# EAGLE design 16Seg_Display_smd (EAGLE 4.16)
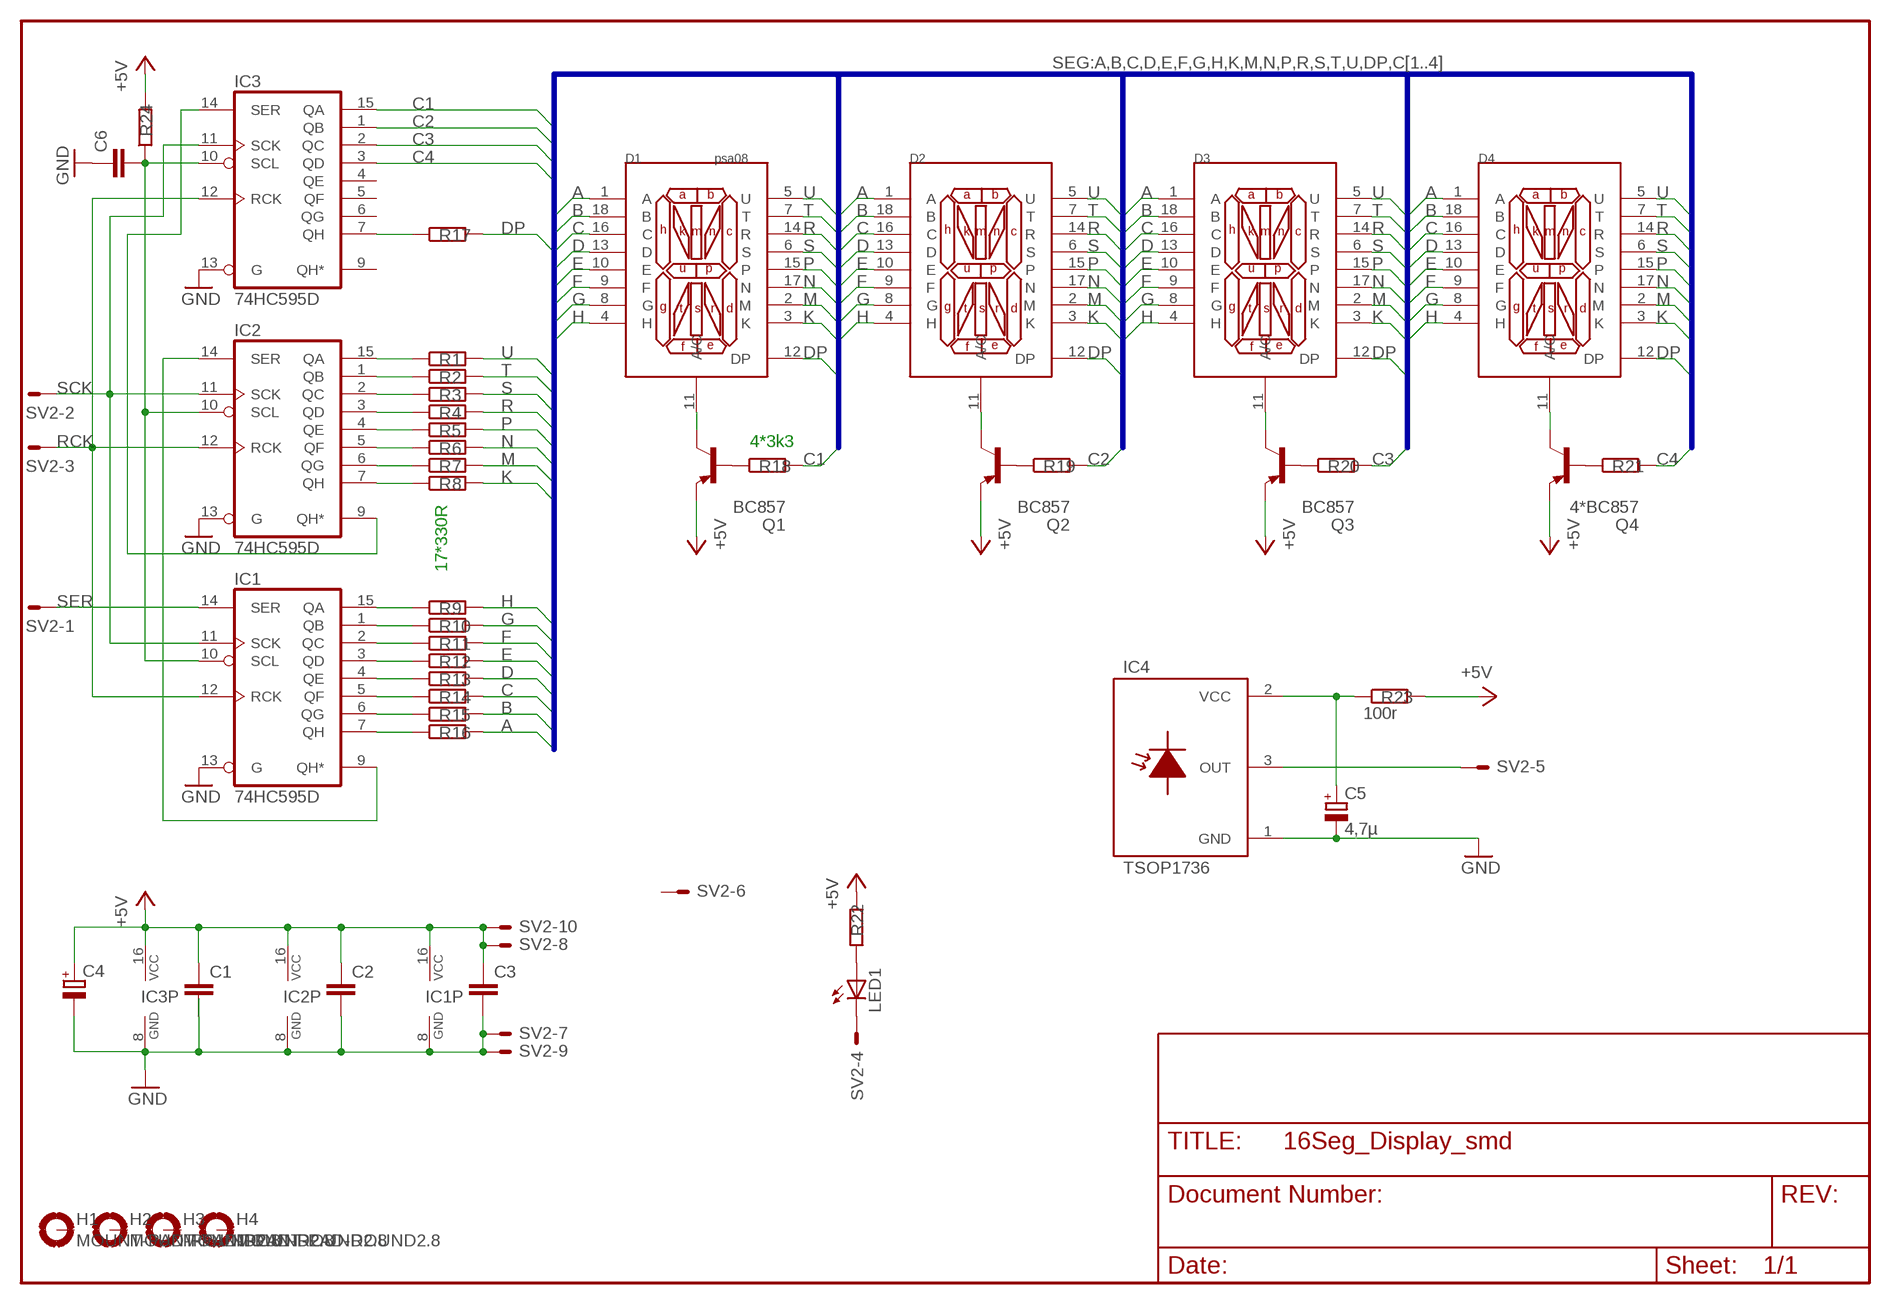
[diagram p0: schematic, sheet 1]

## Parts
C1  C-EUC0805K  [C0805K]
C2  C-EUC0805K  [C0805K]
C3  C-EUC0805K  [C0805K]
C4  CPOL-EUE2-5  [E2-5]
C5  4,7µ  CPOL-EUE2-5  [E2-5]
C6  C-EUC0805K  [C0805K]
D1  psa08  PSA08-11  [MSA08-11]
D2  PSA08-11  [MSA08-11]
D3  PSA08-11  [MSA08-11]
D4  PSA08-11  [MSA08-11]
H1  MOUNT-PAD-ROUND2.8  [2,8-PAD]
H2  MOUNT-PAD-ROUND2.8  [2,8-PAD]
H3  MOUNT-PAD-ROUND2.8  [2,8-PAD]
H4  MOUNT-PAD-ROUND2.8  [2,8-PAD]
IC1  74HC595D  [SO16]
IC2  74HC595D  [SO16]
IC3  74HC595D  [SO16]
IC4  TSOP1736  [TSOP]
LED1  LED3MM  [LED3MM]
Q1  BC857  BC857BSMD  [SOT23-BEC]
Q2  BC857  BC857BSMD  [SOT23-BEC]
Q3  BC857  BC857BSMD  [SOT23-BEC]
Q4  4*BC857  BC857BSMD  [SOT23-BEC]
R1  R-EU_M0805  [M0805]
R2  R-EU_M0805  [M0805]
R3  R-EU_M0805  [M0805]
R4  R-EU_M0805  [M0805]
R5  R-EU_M0805  [M0805]
R6  R-EU_M0805  [M0805]
R7  R-EU_M0805  [M0805]
R8  R-EU_M0805  [M0805]
R9  R-EU_M0805  [M0805]
R10  R-EU_M0805  [M0805]
R11  R-EU_M0805  [M0805]
R12  R-EU_M0805  [M0805]
R13  R-EU_M0805  [M0805]
R14  R-EU_M0805  [M0805]
R15  R-EU_M0805  [M0805]
R16  R-EU_M0805  [M0805]
R17  R-EU_M0805  [M0805]
R18  R-EU_M0805  [M0805]
R19  R-EU_M0805  [M0805]
R20  R-EU_M0805  [M0805]
R21  R-EU_M0805  [M0805]
R22  R-EU_M0805  [M0805]
R23  100r  R-EU_M0805  [M0805]
R24  R-EU_M0805  [M0805]
SV2  ML10E  [ML10]

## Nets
+5V: C1.1 C2.1 C3.1 C4.+ IC1.16(VCC) IC2.16(VCC) IC3.16(VCC) Q1.E Q2.E Q3.E Q4.E R22.2 R23.2 R24.2 SV2.8 SV2.10
A: D1.1(A) D2.1(A) D3.1(A) D4.1(A) R16.2
B: D1.18(B) D2.18(B) D3.18(B) D4.18(B) R15.2
C: D1.16(C) D2.16(C) D3.16(C) D4.16(C) R14.2
C1: IC3.15(QA) R18.2
C2: IC3.1(QB) R19.2
C3: IC3.2(QC) R20.2
C4: IC3.3(QD) R21.2
D: D1.13(D) D2.13(D) D3.13(D) D4.13(D) R13.2
DP: D1.12(DP) D2.12(DP) D3.12(DP) D4.12(DP) R17.2
E: D1.10(E) D2.10(E) D3.10(E) D4.10(E) R12.2
F: D1.9(F) D2.9(F) D3.9(F) D4.9(F) R11.2
G: D1.8(G) D2.8(G) D3.8(G) D4.8(G) R10.2
GND: C1.2 C2.2 C3.2 C4.- C5.- C6.1 IC1.8(GND) IC1.13(G) IC2.8(GND) IC2.13(G) IC3.8(GND) IC3.13(G) IC4.1(GND) SV2.7 SV2.9
H: D1.4(H) D2.4(H) D3.4(H) D4.4(H) R9.2
K: D1.3(K) D2.3(K) D3.3(K) D4.3(K) R8.2
M: D1.2(M) D2.2(M) D3.2(M) D4.2(M) R7.2
N: D1.17(N) D2.17(N) D3.17(N) D4.17(N) R6.2
N$1: Q1.B R18.1
N$2: IC1.9(QH*) IC2.14(SER)
N$3: IC2.9(QH*) IC3.14(SER)
N$4: Q2.B R19.1
N$5: Q3.B R20.1
N$6: IC1.15(QA) R9.1
N$7: IC1.1(QB) R10.1
N$8: IC1.2(QC) R11.1
N$9: IC1.3(QD) R12.1
N$10: IC1.4(QE) R13.1
N$11: IC1.5(QF) R14.1
N$12: IC1.6(QG) R15.1
N$13: IC1.7(QH) R16.1
N$14: IC2.15(QA) R1.1
N$15: IC2.1(QB) R2.1
N$16: IC2.2(QC) R3.1
N$17: IC2.3(QD) R4.1
N$18: IC2.4(QE) R5.1
N$19: IC2.5(QF) R6.1
N$20: IC2.6(QG) R7.1
N$21: IC2.7(QH) R8.1
N$22: IC3.7(QH) R17.1
N$23: Q4.B R21.1
N$24: LED1.A R22.1
N$25: D1.11(A/C) Q1.C
N$26: D2.11(A/C) Q2.C
N$27: D3.11(A/C) Q3.C
N$28: D4.11(A/C) Q4.C
N$29: LED1.K(C) SV2.4
N$30: IC4.3(OUT) SV2.5
N$31: C5.+ IC4.2(VCC) R23.1
N$33: C6.2 IC1.10(SCL) IC2.10(SCL) IC3.10(SCL) R24.1
P: D1.15(P) D2.15(P) D3.15(P) D4.15(P) R5.2
R: D1.14(R) D2.14(R) D3.14(R) D4.14(R) R4.2
RCK: IC1.12(RCK) IC2.12(RCK) IC3.12(RCK) SV2.3
S: D1.6(S) D2.6(S) D3.6(S) D4.6(S) R3.2
SCK: IC1.11(SCK) IC2.11(SCK) IC3.11(SCK) SV2.2
SER: IC1.14(SER) SV2.1
T: D1.7(T) D2.7(T) D3.7(T) D4.7(T) R2.2
U: D1.5(U) D2.5(U) D3.5(U) D4.5(U) R1.2
Unconnected: H1.B2,8(MOUNT) H2.B2,8(MOUNT) H3.B2,8(MOUNT) H4.B2,8(MOUNT) IC3.4(QE) IC3.5(QF) IC3.6(QG) IC3.9(QH*) SV2.6

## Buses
SEG:A,B,C,D,E,F,G,H,K,M,N,P,R,S,T,U,DP,C[1..4]

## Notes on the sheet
- 4*3k3
- 17*330R

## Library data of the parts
C1-C3 C6 = rcl:C-EU: CAPACITOR, European symbol
C4 C5 = rcl:CPOL-EU: POLARIZED CAPACITOR, European symbol
D1-D4 = 16seg:PSA08-11
H1-H4 = holes:MOUNT-PAD-ROUND: MOUNTING PAD, round
IC1-IC3 = 74xx-eu:74*595: 8-bit SHIFT REGISTER, output latch
IC4 = andereBauteile:TSOP: TSOP17.. Photo Modules for PCM Remote Control Systems
LED1 = led:LED: LED
Q1-Q4 = transistor-pnp:BC857*: PNP Transistror
R1-R24 = rcl:R-EU_: RESISTOR, European symbol
SV2 = con-harting-ml:ML10?E: HARTING

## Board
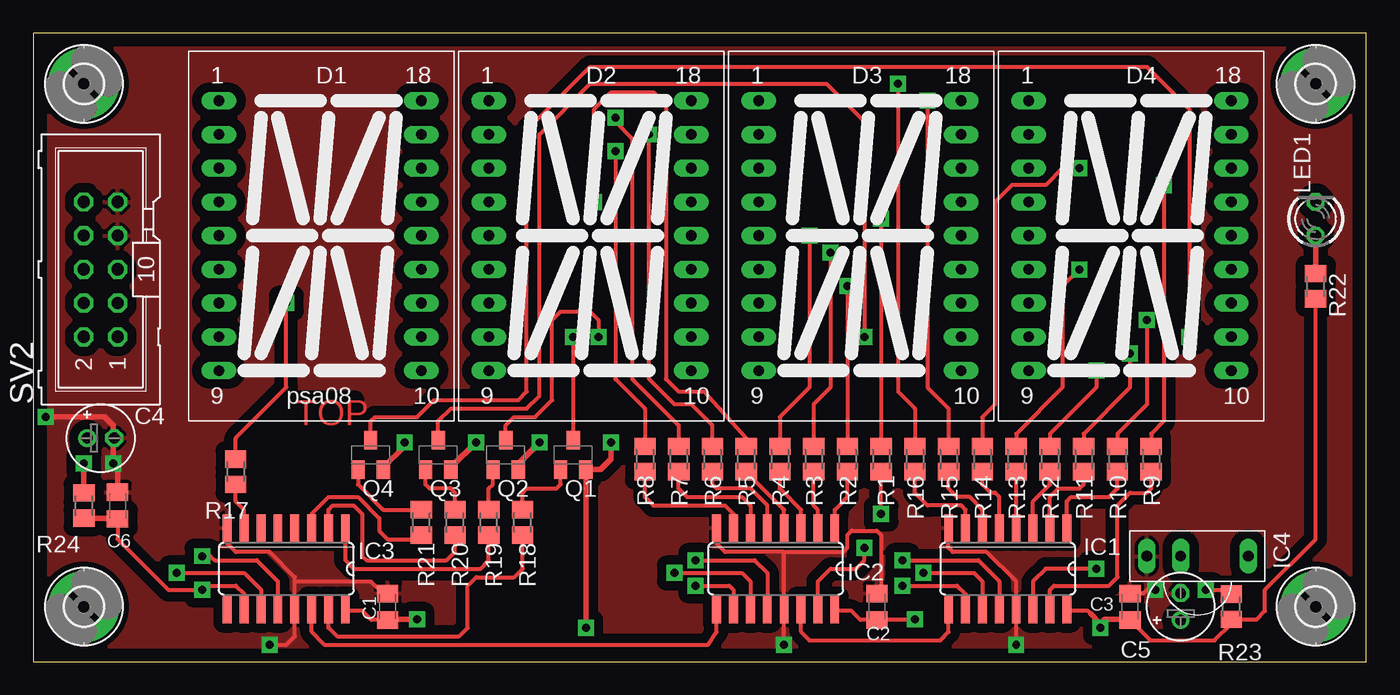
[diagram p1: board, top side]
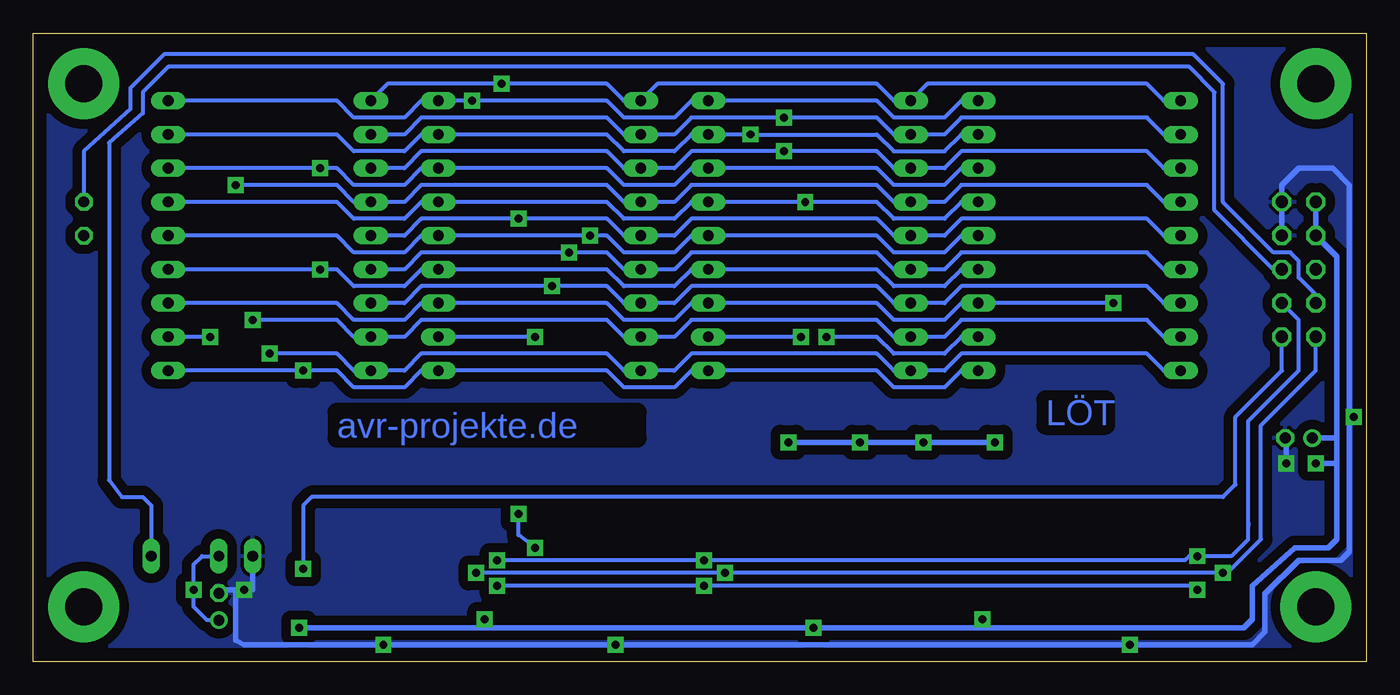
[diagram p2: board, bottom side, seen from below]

Size 100.33 x 47.31 mm. Coordinates in mm from the lower left corner, seen from the top.
Outline: 0,0 100.33,0 100.33,47.31 0,47.31 0,0
Copper layers (1*16): Top 0.035mm / dielectric 1.5mm / Bottom 0.035mm
Design rules "default": minimum track width 10mil, minimum drill 0.4mm, track to track 28mil, track to pad 28mil, pad to pad 10mil, via to via 10mil, smd to smd 10mil, copper to edge 40mil, drill to drill 8mil, minimum pad ring 10mil, minimum via ring 0.3mm, stop-mask expansion 4mil, vias tented up to drill 0mil, thermal gap 10mil

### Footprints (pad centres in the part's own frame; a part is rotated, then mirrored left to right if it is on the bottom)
C0805K = smd 1.3 x 1.6: 1 -1,0; 2 1,0
E2-5 = drill 0.813 pad 1.27 round: + -1.016,0 | drill 0.813 pad 1.27 octagon: - 1.016,0
MSA08-11 = drill 0.8 long: 1 -7.62,10.16; 2 -7.62,7.62; 3 -7.62,5.08; 4 -7.62,2.54; 5 -7.62,0; 6 -7.62,-2.54; 7 -7.62,-5.08; 8 -7.62,-7.62; 9 -7.62,-10.16; 10 7.62,-10.16; 11 7.62,-7.62; 12 7.62,-5.08; 13 7.62,-2.54; 14 7.62,0; 15 7.62,2.54; 16 7.62,5.08; 17 7.62,7.62; 18 7.62,10.16
2,8-PAD = drill 2.8 pad 5.334 round: B2,8 0,0
SO16 = smd 0.66 x 2.032: 1 -4.445,-3.073; 2 -3.175,-3.073; 3 -1.905,-3.073; 4 -0.635,-3.073; 5 0.635,-3.073; 6 1.905,-3.073; 7 3.175,-3.073; 8 4.445,-3.073; 9 4.445,3.073; 10 3.175,3.073; 11 1.905,3.073; 12 0.635,3.073; 13 -0.635,3.073; 14 -1.905,3.073; 15 -3.175,3.073; 16 -4.445,3.073
TSOP = drill 0.813 long: 1 3.81,0; 2 1.27,0; 3 -3.81,0
LED3MM = drill 0.813 octagon: A -1.27,0; K 1.27,0
SOT23-BEC = smd 1 x 1.4: B -0.95,-1.1; C 0,1.1; E 0.95,-1.1
M0805 = smd 1.3 x 1.6: 1 -0.95,0; 2 0.95,0
ML10 = drill 0.914 octagon: 1 -5.08,-1.27; 2 -5.08,1.27; 3 -2.54,-1.27; 4 -2.54,1.27; 5 0,-1.27; 6 0,1.27; 7 2.54,-1.27; 8 2.54,1.27; 9 5.08,-1.27; 10 5.08,1.27

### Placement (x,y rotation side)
C1  26.67,4.13 90 top
C2  63.5,4.13 90 top
C3  82.55,4.13 90 top
C4  5.08,16.83 0 top
C5  86.36,4.13 90 top
C6  6.35,11.75 270 top
D1  21.59,32.07 0 top
D2  41.91,32.07 0 top
D3  62.23,32.07 0 top
D4  82.55,32.07 0 top
H1  3.81,4.13 0 top
H2  3.81,43.5 0 top
H3  96.52,4.13 0 top
H4  96.52,43.5 0 top
IC1  73.34,6.99 180 top
IC2  55.88,6.99 180 top
IC3  19.05,6.99 180 top
IC4  87.63,7.94 180 top
LED1  96.52,33.34 90 top
Q1  40.64,15.56 0 top
Q2  35.56,15.56 0 top
Q3  30.48,15.56 0 top
Q4  25.4,15.56 0 top
R1  63.82,15.24 90 top
R2  61.28,15.24 90 top
R3  58.74,15.24 90 top
R4  56.2,15.24 90 top
R5  53.66,15.24 90 top
R6  51.12,15.24 90 top
R7  48.58,15.24 90 top
R8  46.04,15.24 90 top
R9  84.14,15.24 90 top
R10  81.6,15.24 90 top
R11  79.06,15.24 90 top
R12  76.52,15.24 90 top
R13  73.98,15.24 90 top
R14  71.44,15.24 90 top
R15  68.9,15.24 90 top
R16  66.36,15.24 90 top
R17  15.24,14.29 90 top
R18  36.83,10.48 270 top
R19  34.29,10.48 270 top
R20  31.75,10.48 270 top
R21  29.21,10.48 270 top
R22  96.52,28.26 270 top
R23  90.17,4.13 270 top
R24  3.81,11.75 90 top
SV2  5.08,29.53 90 top

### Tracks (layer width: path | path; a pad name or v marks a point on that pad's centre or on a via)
+5V  (via drill 0.6)
  Top 0.305: C3.1 84.09,1.59 88.9,1.59 90.17,2.86 R23.2 | C1.1 25.45,3.13 24.77,3.81 23.5,3.81 IC3.16 | v41.59,2.54 | Q1.E 41.59,14.61 | Q4.E 26.35,14.92 | R22.2 96.52,9.21 92.71,5.4 92.71,3.81 92.08,3.17 R23.2 | R23.2 | IC2.16 60.33,3.81 61.59,3.81 62.28,3.13 C2.1 66.31,3.13 v66.36,3.17 | 79.59,3.59 79.38,3.81 77.79,3.81 IC1.16
  Top 0.406: C3.1 82.55,3.17 80.64,3.17 80.33,2.86 | 80.33,2.86 79.59,3.59 | v80.33,2.54 80.33,2.86 | v3.81,14.92 R24.2 | v41.59,2.54 Q1.E 42.72,14.46 43.5,15.24 v43.5,16.51 | C1.1 26.67,3.17 v28.89,3.17 | Q4.E 26.35,14.6 27.94,16.19 v27.94,16.51 | Q3.E 31.43,14.6 v33.34,16.51 | Q2.E 36.51,14.92 v38.1,16.51
  Bottom 0.305: 66.36,2.54 v66.36,3.17 | 28.89,2.54 v28.89,3.17
  Bottom 0.406: SV2.10 SV2.8 2.22,30.48 2.22,16.83 | 2.22,14.92 2.22,9.21 2.86,8.57 5.4,8.57 8.57,5.71 8.57,3.17 9.21,2.54 28.89,2.54 v41.59,2.54 66.36,2.54 v80.33,2.54 | 2.22,14.92 2.22,16.83 | 2.22,16.83 C4.+ | 2.22,14.92 v3.81,14.92 | v43.5,16.51 v38.1,16.51 v33.34,16.51 v27.94,16.51
A  (via drill 0.6)
  Top 0.305: v65.09,43.5 65.09,20.32 66.36,19.05 R16.2 66.36,15.87
  Bottom 0.305: D1.1 15.24,42.23 16.51,43.5 33.02,43.5 D2.1 35.56,42.23 36.83,43.5 53.34,43.5 D3.1 55.88,42.23 57.15,43.5 v65.09,43.5 73.66,43.5 D4.1
B  (via drill 0.6)
  Top 0.305: v67.31,42.23 67.31,20.64 68.9,19.05 R15.2
  Bottom 0.305: D1.18 30.48,42.23 31.75,40.96 35.56,40.96 36.83,42.23 D2.18 50.8,42.23 52.07,40.96 55.88,40.96 57.15,42.23 v67.31,42.23 D3.18 71.12,42.23 72.39,40.96 76.2,40.96 77.47,42.23 D4.18
C  (via drill 0.6)
  Top 0.305: R14.2 71.44,18.42 72.39,19.37 72.39,34.61 73.66,35.88 76.2,35.88 77.47,37.15 v78.74,37.15
  Bottom 0.305: D1.16 30.48,37.15 31.75,35.88 35.56,35.88 36.83,37.15 D2.16 50.8,37.15 52.07,35.88 55.88,35.88 57.15,37.15 D3.16 71.12,37.15 72.39,35.88 76.2,35.88 77.47,37.15 v78.74,37.15 D4.16
C1
  Top 0.305: IC3.15 22.23,2.54 22.86,1.9 32.07,1.9 32.7,2.54 32.7,5.71 33.34,6.35 36.2,6.35 36.83,6.99 R18.2
C2
  Top 0.305: IC3.1 23.5,7.62 24.13,6.99 33.66,6.99 34.29,7.62 R19.2
C3
  Top 0.305: IC3.2 22.23,11.43 22.54,11.75 24.13,11.75 24.77,11.11 24.77,7.94 25.08,7.62 31.11,7.62 31.75,8.26 R20.2
C4
  Top 0.305: IC3.3 20.95,11.11 22.23,12.38 24.45,12.38 26.04,10.79 26.04,9.84 26.67,9.21 28.89,9.21 R21.2
D  (via drill 0.6)
  Top 0.305: R13.2 73.98,17.15 77.47,20.64 77.47,28.26 v78.74,29.53
  Bottom 0.305: D1.13 30.48,29.53 31.75,28.26 35.56,28.26 36.83,29.53 D2.13 50.8,29.53 52.07,28.26 55.88,28.26 57.15,29.53 D3.13 71.12,29.53 72.39,28.26 76.2,28.26 77.47,29.53 v78.74,29.53 D4.13
DP  (via drill 0.6)
  Top 0.305: v19.05,26.99 19.05,20.64 15.24,16.83 R17.2
  Bottom 0.305: v19.05,26.99 D1.12 30.48,26.99 31.75,25.72 35.56,25.72 36.83,26.99 D2.12 50.8,26.99 52.07,25.72 55.88,25.72 57.15,26.99 D3.12 71.12,26.99 72.39,25.72 76.2,25.72 77.47,26.99 D4.12
E  (via drill 0.6)
  Top 0.305: R12.2 76.52,17.15 80.01,20.64 v80.01,21.91
  Bottom 0.305: D4.10 v80.01,21.91 77.47,21.91 76.2,20.64 72.39,20.64 71.12,21.91 D3.10 57.15,21.91 55.88,20.64 52.07,20.64 50.8,21.91 D2.10 36.83,21.91 35.56,20.64 31.75,20.64 30.48,21.91 D1.10
F  (via drill 0.6)
  Top 0.305: v82.55,23.18 82.55,20.64 79.06,17.15 R11.2
  Bottom 0.305: D1.9 15.24,21.91 16.51,23.18 30.48,23.18 31.75,21.91 D2.9 35.56,21.91 36.83,23.18 50.8,23.18 52.07,21.91 D3.9 55.88,21.91 57.15,23.18 71.12,23.18 72.39,21.91 D4.9 76.2,21.91 77.47,23.18 v82.55,23.18
G  (via drill 0.6)
  Top 0.305: v83.82,25.72 83.82,19.37 81.6,17.15 R10.2
  Bottom 0.305: D1.8 15.24,24.45 16.51,25.72 30.48,25.72 31.75,24.45 D2.8 35.56,24.45 36.83,25.72 50.8,25.72 52.07,24.45 D3.8 55.88,24.45 57.15,25.72 71.12,25.72 72.39,24.45 D4.8 76.2,24.45 77.47,25.72 v83.82,25.72
GND  (via drill 0.6)
  Top 0.305: v17.78,1.27 19.05,1.27 19.68,1.9 IC3.13 | IC3.13 19.68,4.13 | IC3.13 19.68,6.03 | 19.68,6.03 19.68,6.35 17.78,8.26 15.24,8.26 14.61,8.89 IC3.8 | C1.2 26.3,5.13 25.4,6.03 19.68,6.03 | IC2.8 51.44,8.89 52.07,8.26 56.52,8.26 | v56.52,1.27 IC2.13 56.52,8.26 | v73.98,1.27 IC1.13 73.98,6.03 71.75,8.26 69.22,8.26 68.9,8.57 IC1.8 | C3.2 83.55,5.13 83.82,5.4 v84.45,5.4 | 56.52,8.26 60.96,8.26 61.28,8.57 61.28,9.52 61.59,9.84 63.5,9.84 63.82,9.52 63.82,5.4 63.5,5.08 C2.2
  Top 0.406: 6.35,12.7 C6.1 6.35,14.6 v6.03,14.92 6.03,17.78 5.4,18.42 v0.95,18.42
  Bottom 0.406: SV2.7 SV2.9 6.35,35.88 5.08,37.15 2.54,37.15 1.27,35.88 1.27,18.42 | 85.09,5.4 v84.45,5.4 83.82,5.4 IC4.1 | 1.27,18.42 1.27,8.26 1.91,7.62 5.08,7.62 7.62,5.08 7.62,2.22 8.57,1.27 v17.78,1.27 v56.52,1.27 v73.98,1.27 84.45,1.27 85.09,1.59 85.09,5.4 | C4.- 6.03,16.76 v6.03,14.92 | 1.27,18.42 v0.95,18.42 | C5.- 86.11,5.4 85.09,5.4
  pour Bottom: 0,47.31 0,0 100.33,0 100.33,47.31
  pour Top: 0,47.31 0,0 100.33,0 100.33,47.31
H  (via drill 0.6)
  Top 0.305: R9.2 84.14,17.15 85.09,18.1 v85.09,35.88
  Bottom 0.305: D1.4 15.24,34.61 16.51,35.88 30.48,35.88 31.75,34.61 D2.4 35.56,34.61 36.83,35.88 50.8,35.88 52.07,34.61 D3.4 55.88,34.61 57.15,35.88 71.12,35.88 72.39,34.61 D4.4 76.2,34.61 77.47,35.88 v85.09,35.88
K  (via drill 0.6)
  Top 0.305: v43.81,38.42 43.81,21.27 46.04,19.05 R8.2
  Bottom 0.305: D1.3 15.24,37.15 16.51,38.42 30.48,38.42 31.75,37.15 D2.3 35.56,37.15 36.83,38.42 v43.81,38.42 50.8,38.42 52.07,37.15 D3.3 55.88,37.15 57.15,38.42 71.12,38.42 72.39,37.15 D4.3
M  (via drill 0.6)
  Top 0.305: v43.81,40.96 43.81,40.64 45.09,39.37 45.09,21.27 48.58,17.78 R7.2
  Bottom 0.305: D1.2 15.24,39.69 16.51,40.96 30.48,40.96 31.75,39.69 D2.2 35.56,39.69 36.83,40.96 v43.81,40.96 50.8,40.96 52.07,39.69 D3.2 55.88,39.69 57.15,40.96 71.12,40.96 72.39,39.69 D4.2
N  (via drill 0.6)
  Top 0.305: R6.2 51.12,16.51 | R6.2 | v46.35,39.69 46.35,21.27 48.26,19.37 49.53,19.37 51.12,17.78 R6.2
  Bottom 0.305: D1.17 30.48,39.69 31.75,38.42 35.56,38.42 36.83,39.69 v46.35,39.69 D2.17 50.8,39.69 52.07,38.42 55.88,38.42 57.15,39.69 D3.17 71.12,39.69 72.39,38.42 76.2,38.42 77.47,39.69 D4.17
N$1
  Top 0.305: Q1.B 39.69,13.34 39.37,13.02 37.15,13.02 36.83,12.7 R18.1
N$2
  Top 0.305: IC2.14 57.78,2.22 58.42,1.59 68.26,1.59 68.9,2.22 IC1.9 68.9,4.13
N$3
  Top 0.305: IC3.14 20.95,2.22 21.91,1.27 50.8,1.27 51.44,2.22 IC2.9
N$4
  Top 0.305: Q2.B 34.61,13.34 34.29,13.02 R19.1
N$5
  Top 0.305: Q3.B 29.53,13.33 29.84,13.02 31.43,13.02 31.75,12.7 R20.1
N$6
  Top 0.305: R9.1 84.14,13.02 83.82,12.7 82.55,12.7 81.6,11.75 81.6,6.35 80.96,5.71 76.83,5.71 76.52,5.4 IC1.15
N$7
  Top 0.305: R10.1 81.6,13.02 80.96,12.38 78.11,12.38 77.79,12.07 IC1.1
N$8
  Top 0.305: R11.1 79.06,13.34 78.74,13.02 77.15,13.02 76.52,12.38 IC1.2
N$9
  Top 0.305: IC1.3 75.25,12.07 76.52,13.34 R12.1
N$10
  Top 0.305: IC1.4 R13.1
N$11
  Top 0.305: R14.1 71.44,13.34 72.07,12.7 72.39,12.7 72.71,12.38 IC1.5
N$12
  Top 0.305: IC1.6 71.44,11.43 70.48,12.38 69.53,12.38 68.9,13.02 R15.1
N$13
  Top 0.305: R16.1 66.36,12.7 67.31,11.75 69.85,11.75 70.17,11.43 IC1.7
N$14  (via drill 0.6)
  Top 0.305: IC2.15 59.05,6.03 60.01,6.99 61.91,6.99 62.55,7.62 v62.55,8.57 | v63.82,11.11 R1.1
  Bottom 0.305: v62.55,8.57 63.82,9.52 v63.82,11.11
N$15
  Top 0.305: IC2.1 60.33,11.43 61.28,12.38 R2.1
N$16
  Top 0.305: IC2.2 59.05,11.43 58.74,11.75 R3.1
N$17
  Top 0.305: IC2.3 57.78,11.43 56.2,13.02 R4.1
N$18
  Top 0.305: R5.1 56.52,11.43 IC2.4
N$19
  Top 0.305: IC2.5 55.24,11.75 53.98,13.02 51.44,13.02 51.12,13.34 R6.1
N$20
  Top 0.305: IC2.6 53.98,11.75 53.34,12.38 49.21,12.38 48.58,13.02 R7.1
N$21
  Top 0.305: IC2.7 52.7,11.11 52.07,11.75 46.67,11.75 46.04,12.38 R8.1
N$22
  Top 0.305: IC3.7 15.88,11.43 15.24,12.07 R17.1
N$23
  Top 0.305: Q4.B 24.45,13.33 26.35,11.43 R21.1
N$24
  Top 0.406: R22.1 LED1.A
N$25  (via drill 0.6)
  Top 0.305: v40.64,24.45 Q1.C
  Bottom 0.305: D1.11 30.48,24.45 31.75,23.18 35.56,23.18 36.83,24.45 v40.64,24.45
N$26  (via drill 0.6)
  Top 0.305: 35.56,16.51 Q2.C 35.56,17.78 36.2,18.42 37.78,18.42 39.05,19.68 39.05,25.72 39.69,26.35 41.91,26.35 42.55,25.72 v42.55,24.45
  Bottom 0.305: v42.55,24.45 D2.11
N$27  (via drill 0.6)
  Top 0.305: v62.55,24.45 62.55,40.64 59.69,43.5 41.91,43.5 38.1,39.69 38.1,20 37.15,19.05 31.43,19.05 30.48,18.1 Q3.C 30.48,16.51
  Bottom 0.305: v62.55,24.45 D3.11
N$28  (via drill 0.6)
  Top 0.305: Q4.C 25.4,18.1 25.72,18.42 28.89,18.42 30.16,19.68 36.51,19.68 37.15,20.32 37.15,40.01 41.91,44.77 83.82,44.77 87,41.59 v87,24.45
  Bottom 0.305: v87,24.45 D4.11
N$29
  Bottom 0.305: SV2.4 3.81,27.62 5.08,28.89 5.08,30.16 5.71,30.8 6.99,30.8 10.79,34.61 10.79,43.5 13.02,45.72 90.49,45.72 93.03,43.18 93.03,41.59 96.52,38.42 LED1.K
N$30
  Bottom 0.305: SV2.5 6.99,29.53 11.43,33.97 11.43,42.86 13.34,44.77 90.17,44.77 92.08,42.86 92.08,41.28 94.61,39.05 94.61,13.65 93.66,12.38 92.08,12.38 91.44,11.75 IC4.3
N$31  (via drill 0.6)
  Top 0.305: R23.1 89.85,5.4 v88.27,5.4
  Bottom 0.305: C5.+ 87.25,3.11 88.27,4.13 v88.27,5.4 88.27,7.3 87.63,7.94 IC4.2
N$33  (via drill 0.6)
  Top 0.305: v65.41,5.71 69.53,5.71 70.17,5.08 IC1.10 70.17,3.81 | IC3.10 15.88,5.08 15.24,5.71 12.7,5.71 v12.7,5.4 10.16,5.4 6.35,9.21 C6.2 | v49.85,5.71 52.39,5.71 52.7,5.4 IC2.10 52.7,3.81
  Top 0.406: C6.2 6.35,10.79 R24.1
  Bottom 0.305: v12.7,5.4 12.7,5.71 v49.85,5.71 v65.41,5.71
P  (via drill 0.6)
  Top 0.305: v42.23,34.61 42.23,41.59 43.5,42.86 46.67,42.86 47.62,41.91 47.62,21.27 48.58,20.32 50.48,20.32 53.66,16.83 R5.2
  Bottom 0.305: D1.15 30.48,34.61 31.75,33.34 35.56,33.34 36.83,34.61 v42.23,34.61 D2.15 50.8,34.61 52.07,33.34 55.88,33.34 57.15,34.61 D3.15 71.12,34.61 72.39,33.34 76.2,33.34 77.47,34.61 D4.15
R  (via drill 0.6)
  Top 0.305: v58.42,32.07 58.42,20.64 56.2,18.42 R4.2
  Bottom 0.305: D1.14 30.48,32.07 31.75,30.8 35.56,30.8 36.83,32.07 D2.14 50.8,32.07 52.07,30.8 55.88,30.8 57.15,32.07 v58.42,32.07 D3.14 71.12,32.07 72.39,30.8 76.2,30.8 77.47,32.07 D4.14
RCK  (via drill 0.6)
  Top 0.305: IC3.12 18.41,6.03 16.83,7.62 13.65,7.62 13.34,7.94 v12.7,7.94 | IC1.12 72.71,6.03 71.12,7.62 v65.41,7.62 | v49.85,7.62 54.29,7.62 55.24,6.67 IC2.12 55.24,3.81
  Bottom 0.305: 8.89,10.48 8.89,10.16 | 8.89,10.48 8.89,16.83 | 8.89,16.83 8.89,17.46 | SV2.3 5.08,25.72 5.08,21.91 8.89,18.1 8.89,16.83 | v65.41,7.62 v49.85,7.62 13.65,7.62 13.34,7.94 v12.7,7.94 10.16,7.94 8.89,9.21 8.89,10.48
S  (via drill 0.6)
  Top 0.305: v60.01,30.8 60.01,20.64 58.74,19.37 R3.2
  Bottom 0.305: D1.6 15.24,29.53 16.51,30.8 30.48,30.8 31.75,29.53 D2.6 35.56,29.53 36.83,30.8 50.8,30.8 52.07,29.53 D3.6 55.88,29.53 57.15,30.8 v60.01,30.8 71.12,30.8 72.39,29.53 D4.6
SCK  (via drill 0.6)
  Top 0.305: 71.44,3.81 IC1.11 71.44,6.03 70.8,6.67 v66.99,6.67 | IC3.11 17.14,5.4 15.88,6.67 v10.79,6.67 | v48.26,6.67 53.34,6.67 53.98,6.03 IC2.11 53.98,3.81
  Bottom 0.305: v66.99,6.67 v48.26,6.67 v10.79,6.67 10.48,6.67 7.94,9.21 7.94,17.78 3.81,21.91 SV2.2
SER  (via drill 0.6)
  Top 0.305: v80.01,6.99 76.2,6.99 75.25,6.03 IC1.14 75.25,3.81
  Bottom 0.305: v80.01,6.99 80.01,11.75 79.38,12.38 10.79,12.38 9.84,13.34 9.84,18.42 6.35,21.91 SV2.1
T  (via drill 0.6)
  Top 0.305: v61.28,28.26 R2.2
  Bottom 0.305: D1.7 15.24,26.99 16.51,28.26 30.48,28.26 31.75,26.99 D2.7 35.56,26.99 36.83,28.26 50.8,28.26 52.07,26.99 D3.7 55.88,26.99 57.15,28.26 v61.28,28.26 71.12,28.26 72.39,26.99 D4.7
U  (via drill 0.6)
  Top 0.305: v63.82,33.34 R1.2
  Bottom 0.305: D1.5 15.24,32.07 16.51,33.34 30.48,33.34 31.75,32.07 D2.5 35.56,32.07 36.83,33.34 50.8,33.34 52.07,32.07 D3.5 55.88,32.07 57.15,33.34 v63.82,33.34 71.12,33.34 72.39,32.07 D4.5

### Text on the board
Top: TOP
Bottom: LÖT | avr-projekte.de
